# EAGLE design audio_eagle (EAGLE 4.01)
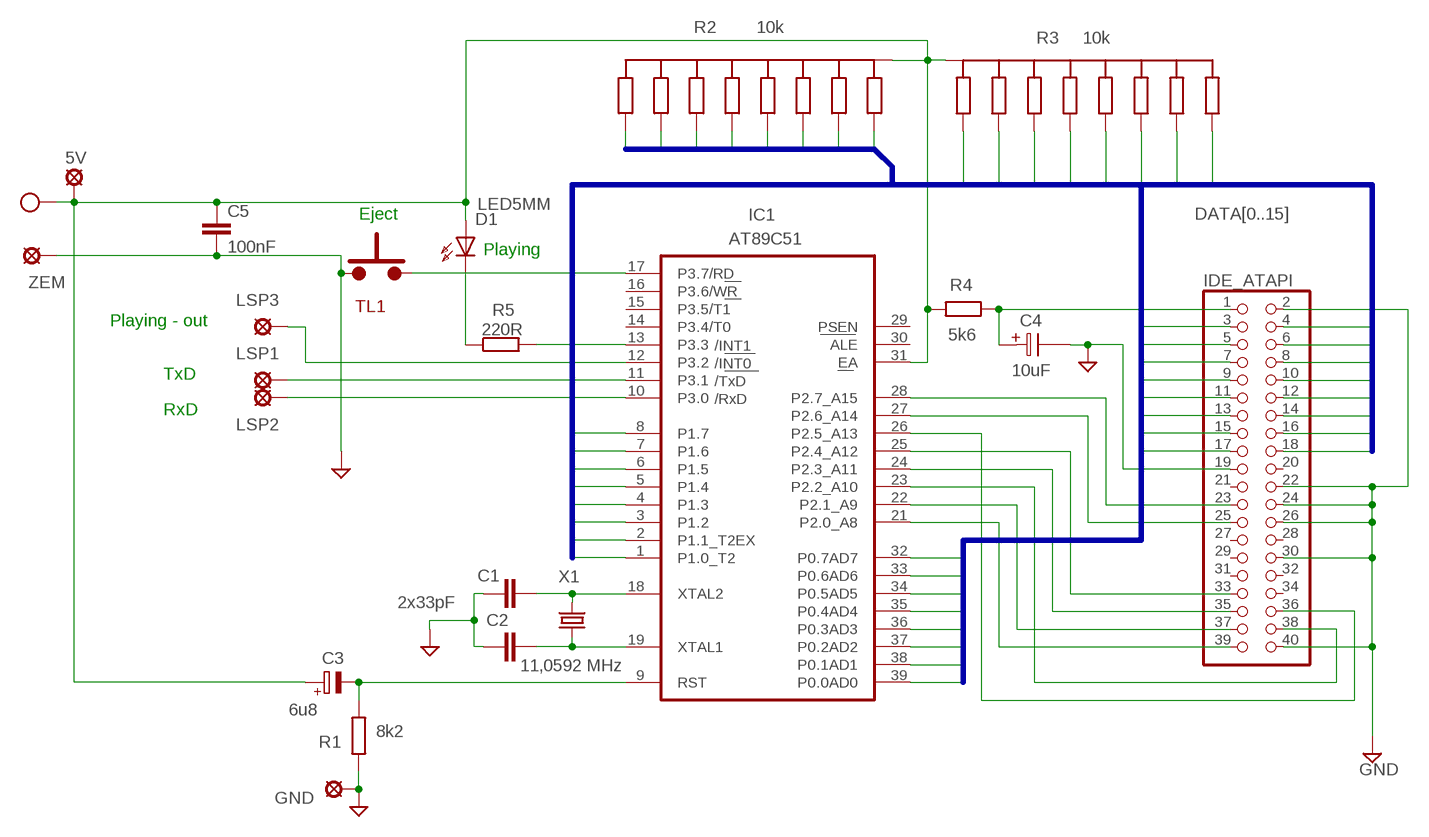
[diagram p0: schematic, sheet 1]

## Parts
5V  5V  LSP10  [LSP10]
C1  C-EU025-025X050  [C025-025X050]
C2  2x33pF  C-EU025-025X050  [C025-025X050]
C3  6u8  E2,5-5  [E2,5-5]
C4  10uF  CT07  [CT07]
C5  100nF  C-EU025-025X050  [C025-025X050]
D1  LED5MM  [LED5MM]
GND  LSP13  [LSP13]
IC1  AT89C51  AT89C52P  [DIL40]
IDE_ATAPI  PINHD-2X20  [2X20]
LSP1  TxD  LSP10  [LSP10]
LSP2  LSP10  [LSP10]
LSP3  LSP10  [LSP10]
R1  8k2  RR-10  [RR-10]
R2  10k  RR8X  [RR8X]
R3  10k  RR8X  [RR8X]
R4  5k6  RR-10  [RR-10]
R5  220R  R-EU_0207/10  [0207/10]
TL1  P-DT6  [P-DT6]
X1  11,0592 MHz  HC49U70  [HC49U70]
ZEM  GND  LSP10  [LSP10]

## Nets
DATA0: IC1.32(P0.7AD7) IDE_ATAPI.17 R2.9
DATA1: IC1.33(P0.6AD6) IDE_ATAPI.15 R2.8
DATA2: IC1.34(P0.5AD5) IDE_ATAPI.13 R2.7
DATA3: IC1.35(P0.4AD4) IDE_ATAPI.11 R2.6
DATA4: IC1.36(P0.3AD3) IDE_ATAPI.9 R2.5
DATA5: IC1.37(P0.2AD2) IDE_ATAPI.7 R2.4
DATA6: IC1.38(P0.1AD1) IDE_ATAPI.5 R2.3
DATA7: IC1.39(P0.0AD0) IDE_ATAPI.3 R2.2
DATA8: IC1.1(P1.0_T2) IDE_ATAPI.4 R3.2
DATA9: IC1.2(P1.1_T2EX) IDE_ATAPI.6 R3.3
DATA10: IC1.3(P1.2) IDE_ATAPI.8 R3.4
DATA11: IC1.4(P1.3) IDE_ATAPI.10 R3.5
DATA12: IC1.5(P1.4) IDE_ATAPI.12 R3.6
DATA13: IC1.6(P1.5) IDE_ATAPI.14 R3.7
DATA14: IC1.7(P1.6) IDE_ATAPI.16 R3.8
DATA15: IC1.8(P1.7) IDE_ATAPI.18 R3.9
GND: C1.2 C2.2 C4.2 C5.1 GND.MP IDE_ATAPI.2 IDE_ATAPI.19 IDE_ATAPI.22 IDE_ATAPI.24 IDE_ATAPI.26 IDE_ATAPI.30 IDE_ATAPI.40 R1.1 TL1.1 ZEM.MP
N$1: C1.1 IC1.18(XTAL2) X1.2
N$2: IC1.13(P3.3) R5.2
N$3: C2.1 IC1.19(XTAL1) X1.1
N$4: IC1.28(P2.7_A15) IDE_ATAPI.23
N$5: C3.- IC1.9(RST) R1.2
N$6: IC1.27(P2.6_A14) IDE_ATAPI.25
N$7: IC1.25(P2.4_A12) IDE_ATAPI.33
N$8: IC1.24(P2.3_A11) IDE_ATAPI.35
N$9: IC1.23(P2.2_A10) IDE_ATAPI.38
N$10: IC1.22(P2.1_A9) IDE_ATAPI.37
N$11: IC1.21(P2.0_A8) IDE_ATAPI.39
N$12: IC1.26(P2.5_A13) IDE_ATAPI.36
N$13: C4.1 IDE_ATAPI.1 R4.1
N$14: IC1.11(P3.1) LSP1.MP
N$15: IC1.10(P3.0) LSP2.MP
N$16: D1.K(C) R5.1
N$17: IC1.12(P3.2) LSP3.MP
N$18: IC1.17(P3.7/RD) TL1.2
VCC: 5V.MP C3.+ C5.2 D1.A IC1.31(EA) R2.1 R3.1 R4.2
Unconnected: IC1.14(P3.4/T0) IC1.15(P3.5/T1) IC1.16(P3.6/WR) IC1.29(PSEN) IC1.30(ALE) IDE_ATAPI.20 IDE_ATAPI.21 IDE_ATAPI.27 IDE_ATAPI.28 IDE_ATAPI.29 IDE_ATAPI.31 IDE_ATAPI.32 IDE_ATAPI.34

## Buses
DATA[0..15]

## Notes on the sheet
- Eject
- Playing
- Playing - out
- TxD
- RxD

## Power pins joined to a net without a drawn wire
GND: IC1.20(GND)
VCC: IC1.40(VCC)

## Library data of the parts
5V LSP1-LSP3 ZEM = solpad:LSP10: SOLDER PAD
C1 C2 C5 = rcl:C-EU: CAPACITOR, European symbol
C3 = polcap:E2,5-5
C4 = GM99:CT07
D1 = led:LED5MM: LED
GND = solpad:LSP13: SOLDER PAD
IC1 = atmel:AT89C52P: MICROCONTROLLER 8 Kbytes FLASH
IDE_ATAPI = pinhead:PINHD-2X20: PIN HEADER
R1 R4 = GM99:RR-10
R2 R3 = GM99:RR8X
R5 = rcl:R-EU_: RESISTOR, European symbol
TL1 = GM99:P-DT6
X1 = crystal:HC49U70: CRYSTAL

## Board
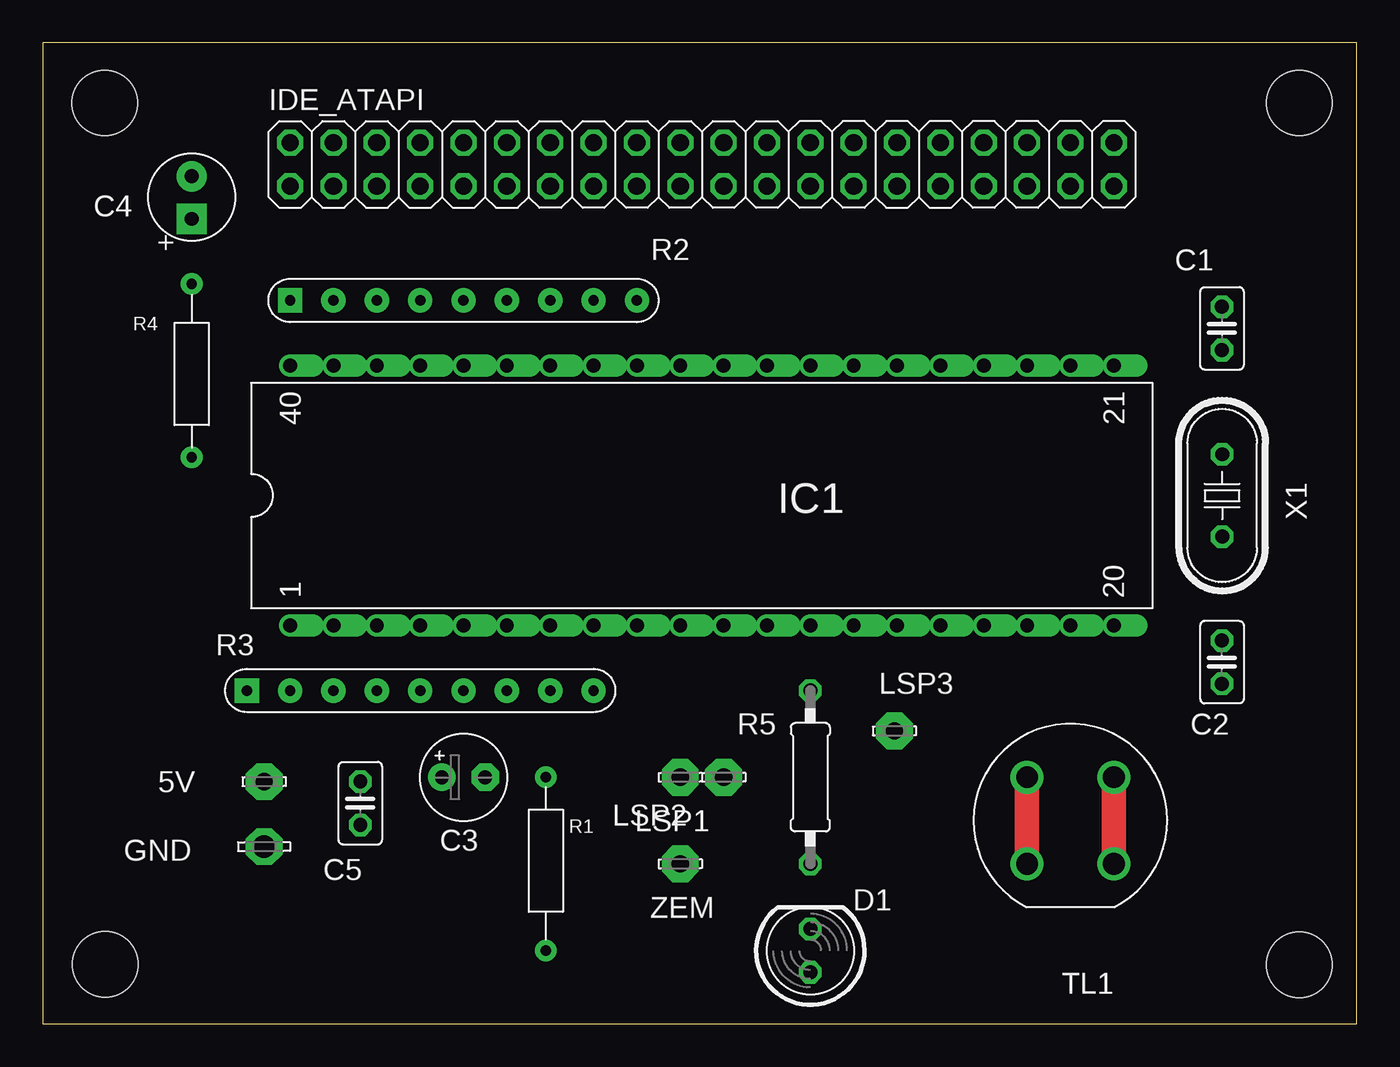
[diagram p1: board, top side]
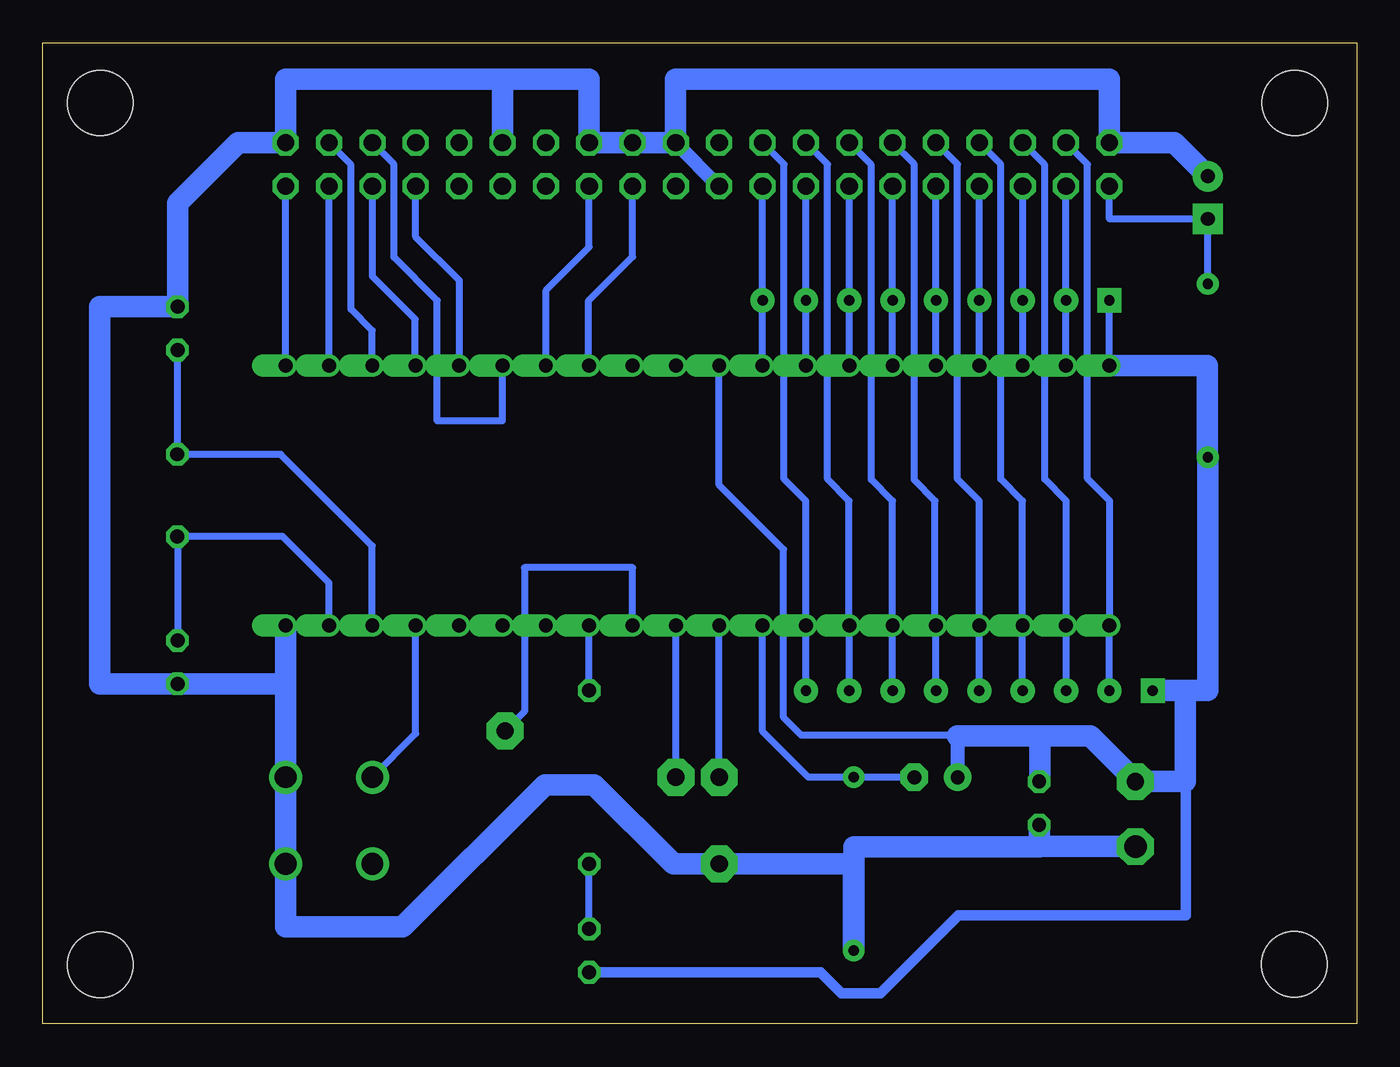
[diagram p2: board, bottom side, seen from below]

Size 77 x 57.5 mm. Coordinates in mm from the lower left corner, seen from the top.
Outline: 0,0 77,0 77,57.5 0,57.5 0,0
Copper layers used: Bottom
Holes 3.81 mm at 3.63,53.97 73.63,53.97 73.63,3.47 3.66,3.5

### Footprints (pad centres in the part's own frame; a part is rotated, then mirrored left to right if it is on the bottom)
LSP10 = drill 1.016 pad 2.159 octagon: MP 0,0
C025-025X050 = drill 0.813 octagon: 1 -1.27,0; 2 1.27,0
E2,5-5 = drill 0.813 pad 1.6 round: + -1.27,0 | drill 0.813 pad 1.6 octagon: - 1.27,0
CT07 = drill 0.813 pad 1.778 square: 1 0,0 | drill 0.813 pad 1.778 round: 2 2.5,0
LED5MM = drill 0.813 octagon: A -1.27,0; K 1.27,0
LSP13 = drill 1.321 pad 2.159 octagon: MP 0,0
DIL40 = drill 0.813 offset: 1 -24.13,-7.62; 2 -21.59,-7.62; 3 -19.05,-7.62; 4 -16.51,-7.62; 5 -13.97,-7.62; 6 -11.43,-7.62; 7 -8.89,-7.62; 8 -6.35,-7.62; 9 -3.81,-7.62; 10 -1.27,-7.62; 11 1.27,-7.62; 12 3.81,-7.62; 13 6.35,-7.62; 14 8.89,-7.62; 15 11.43,-7.62; 16 13.97,-7.62; 17 16.51,-7.62; 18 19.05,-7.62; 19 21.59,-7.62; 20 24.13,-7.62; 21 24.13,7.62; 22 21.59,7.62; 23 19.05,7.62; 24 16.51,7.62; 25 13.97,7.62; 26 11.43,7.62; 27 8.89,7.62; 28 6.35,7.62; 29 3.81,7.62; 30 1.27,7.62; 31 -1.27,7.62; 32 -3.81,7.62; 33 -6.35,7.62; 34 -8.89,7.62; 35 -11.43,7.62; 36 -13.97,7.62; 37 -16.51,7.62; 38 -19.05,7.62; 39 -21.59,7.62; 40 -24.13,7.62
2X20 = drill 1.016 octagon: 1 -24.13,-1.27; 2 -24.13,1.27; 3 -21.59,-1.27; 4 -21.59,1.27; 5 -19.05,-1.27; 6 -19.05,1.27; 7 -16.51,-1.27; 8 -16.51,1.27; 9 -13.97,-1.27; 10 -13.97,1.27; 11 -11.43,-1.27; 12 -11.43,1.27; 13 -8.89,-1.27; 14 -8.89,1.27; 15 -6.35,-1.27; 16 -6.35,1.27; 17 -3.81,-1.27; 18 -3.81,1.27; 19 -1.27,-1.27; 20 -1.27,1.27; 21 1.27,-1.27; 22 1.27,1.27; 23 3.81,-1.27; 24 3.81,1.27; 25 6.35,-1.27; 26 6.35,1.27; 27 8.89,-1.27; 28 8.89,1.27; 29 11.43,-1.27; 30 11.43,1.27; 31 13.97,-1.27; 32 13.97,1.27; 33 16.51,-1.27; 34 16.51,1.27; 35 19.05,-1.27; 36 19.05,1.27; 37 21.59,-1.27; 38 21.59,1.27; 39 24.13,-1.27; 40 24.13,1.27
RR-10 = drill 0.61 pad 1.27 round: 1 0,0; 2 10.16,0
RR8X = drill 0.61 pad 1.422 square: 1 0,0 | drill 0.61 pad 1.422 round: 2 2.54,0; 3 5.08,0; 4 7.62,0; 5 10.16,0; 6 12.7,0; 7 15.24,0; 8 17.78,0; 9 20.32,0
0207/10 = drill 0.813 octagon: 1 -5.08,0; 2 5.08,0
P-DT6 = drill 1.27 pad 1.93 round: 1 0,0; 1A 0,5.08; 2 5.08,0; 2A 5.08,5.08
HC49U70 = drill 0.813 octagon: 1 -2.413,0; 2 2.413,0

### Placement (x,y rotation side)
5V  12.97,14.2 0 top
C1  69.1,40.76 90 top
C2  69.1,21.2 270 top
C3  24.66,14.46 0 top
C4  8.73,47.17 90 top
C5  18.61,12.93 90 top
D1  44.98,4.3 90 top
GND  12.97,10.39 0 top
IC1  38.63,30.97 0 top
IDE_ATAPI  38.63,50.37 0 top
LSP1  39.9,14.46 0 top
LSP2  37.36,14.46 0 top
LSP3  49.91,17.17 0 top
R1  29.48,4.3 90 top
R2  14.5,42.4 0 top
R3  11.96,19.54 0 top
R4  8.73,43.36 270 top
R5  44.98,14.46 90 top
TL1  62.76,14.46 180 top
X1  69.11,30.97 90 top
ZEM  37.36,9.38 0 top

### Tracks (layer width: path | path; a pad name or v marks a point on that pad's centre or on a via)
DATA0
  Bottom 0.406: IC1.32 34.83,38.58 | IC1.32 | IC1.32 R2.9 34.82,49.09 IDE_ATAPI.17 | IDE_ATAPI.17 34.85,49.12 | IDE_ATAPI.17
DATA1
  Bottom 0.406: 32.27,38.59 32.26,38.58 | IC1.33 32.27,38.59 | 32.27,38.59 IC1.33 R2.8 IDE_ATAPI.15 | IDE_ATAPI.15 | IDE_ATAPI.15 32.29,49.12
DATA2
  Bottom 0.406: IC1.34 29.75,38.58 | IC1.34 | IC1.34 R2.7 IDE_ATAPI.13 | IDE_ATAPI.13 | IDE_ATAPI.13 29.72,49.12
DATA3
  Bottom 0.406: R2.6 27.21,42.39 27.2,42.38 IC1.35 | R2.6 | IDE_ATAPI.11 27.2,49.08 27.21,49.07 27.2,49.06 R2.6
DATA4
  Bottom 0.406: 24.66,49.14 IDE_ATAPI.9 | 24.66,49.14 R2.5 IC1.36 | 24.66,49.14 24.67,49.14 | IC1.36 24.67,38.58 | IC1.36
DATA5
  Bottom 0.406: IC1.37 22.12,38.58 | 22.12,38.58 R2.4 22.12,49.06 22.13,49.07 22.12,49.08 IDE_ATAPI.7 | 22.12,38.58 22.13,38.58
DATA6
  Bottom 0.406: 19.58,42.39 R2.3 19.58,49.09 IDE_ATAPI.5 | IC1.38 19.58,42.39 | 19.58,42.39 19.59,42.39
DATA7
  Bottom 0.406: IDE_ATAPI.3 | IDE_ATAPI.3 R2.2 IC1.39 | IDE_ATAPI.3 17.02,49.12 | IC1.39 17.05,38.58 | IC1.39
DATA8
  Bottom 0.406: IC1.1 14.51,23.34 | R3.2 14.51,23.34 | IDE_ATAPI.4 15.78,50.37 15.78,31.95 14.48,30.65 14.48,23.36 14.51,23.34 | 14.51,23.34 IC1.1 | IC1.1
DATA9
  Bottom 0.406: R3.3 17.02,19.54 17.02,23.31 | 17.02,23.34 IC1.2 17.03,23.34 17.02,23.34 | IDE_ATAPI.6 18.29,50.35 18.29,31.92 17.02,30.65 17.02,23.31 | 17.02,23.31 17.02,23.34
DATA10
  Bottom 0.406: R3.4 19.59,23.31 | 19.59,23.31 IC1.3 19.58,23.32 19.59,23.31 | IDE_ATAPI.8 20.86,50.37 20.86,31.92 19.59,30.65 19.59,23.31
DATA11
  Bottom 0.406: R3.5 IC1.4 | IC1.4 22.1,23.36 | IDE_ATAPI.10 23.4,50.37 23.4,31.92 22.13,30.65 22.13,23.31 22.12,23.32 IC1.4
DATA12
  Bottom 0.406: 24.68,23.34 24.69,23.34 24.66,23.3 R3.6 | 24.68,23.34 IC1.5 | IDE_ATAPI.12 25.94,50.37 25.94,31.87 24.72,30.65 24.72,23.39 24.68,23.36 24.68,23.34
DATA13
  Bottom 0.406: IC1.6 | R3.7 IC1.6 | IC1.6 27.21,23.36 | IDE_ATAPI.14 28.45,50.35 28.45,31.9 27.21,30.65 27.21,23.34 IC1.6
DATA14
  Bottom 0.406: R3.8 IC1.7 | IC1.7 29.72,23.36 | IDE_ATAPI.16 31.02,50.37 31.02,31.92 29.75,30.65 29.75,23.34 IC1.7 | IC1.7
DATA15
  Bottom 0.406: IDE_ATAPI.18 33.56,50.37 33.56,31.92 32.29,30.65 32.29,23.34 IC1.8 | IC1.8 | R3.9 32.29,19.53 | R3.9 | IC1.8 R3.9
GND
  Bottom 0.406: 37.39,49.09 IDE_ATAPI.19 | IDE_ATAPI.22 39.9,51.6
  Bottom 0.813: 39.9,51.6 37.39,49.09
  Bottom 1.27: C4.2 | C4.2 10.7,51.63 IDE_ATAPI.2 14.5,55.37 39.91,55.37 IDE_ATAPI.22 | IDE_ATAPI.22 | IDE_ATAPI.22 IDE_ATAPI.24 | IDE_ATAPI.24 42.5,51.63 42.5,51.66 | IDE_ATAPI.26 IDE_ATAPI.24 | IDE_ATAPI.26 44.99,51.66 | IDE_ATAPI.26 44.98,55.37 50.19,55.37 | IDE_ATAPI.30 50.06,55.37 50.19,55.37 | 60.4,55.37 50.19,55.37 | 60.4,55.37 60.48,55.37 | 60.4,55.37 62.76,55.37 IDE_ATAPI.40 65.56,51.63 69.09,48.1 C1.2 | C1.2 69.12,42.01 | C1.2 | C1.2 73.66,42.02 73.66,19.93 C2.2 | C2.2 | C2.2 62.77,19.93 | IC1.20 62.77,19.93 | 62.77,19.93 62.77,14.45 62.76,14.45 TL1.1 62.77,5.68 55.91,5.68 47.58,14.02 44.68,14.02 40.04,9.38 ZEM.MP 29.49,9.38 29.49,4.29 R1.1 29.47,4.29 29.47,10.38 18.61,10.38 C5.1 18.6,11.66 | 18.6,11.66 18.6,11.68 | GND.MP 18.6,10.39 18.6,11.66
N$1
  Bottom 0.406: 57.69,23.34 | IC1.18 57.69,23.34 | 57.69,23.34 57.69,28.01 63.05,33.38 X1.2 | X1.2 | C1.1 69.1,33.37 X1.2
N$2
  Bottom 0.406: R5.2 44.98,19.53 | 44.98,19.53 IC1.13 | 44.98,19.53 44.99,19.53
N$3
  Bottom 0.406: IC1.19 60.22,25.84 62.94,28.57 69.12,28.57 | 69.12,28.57 X1.1 69.11,28.57 69.12,28.57 | C2.1 69.1,28.57 69.12,28.57
N$4
  Bottom 0.406: IDE_ATAPI.23 42.44,44.96 45.01,42.39 45.01,38.6 45,38.6 IC1.28
N$5
  Bottom 0.406: C3.- R1.2 | R1.2 29.49,14.46 29.49,14.45 | IC1.9 34.82,17.13 32.13,14.45 29.49,14.45 | 29.49,14.45 | R1.2 29.49,14.45
N$6
  Bottom 0.406: IDE_ATAPI.25 44.98,45.52 47.5,43 47.5,38.6 IC1.27
N$7
  Bottom 0.406: IDE_ATAPI.33 55.14,46.11 52.58,43.56 52.58,38.57 | 52.58,38.57 52.58,38.55 | IC1.25 52.58,38.57
N$8
  Bottom 0.406: IDE_ATAPI.35 57.68,43.8 55.17,41.3 55.17,38.6 55.16,38.6 IC1.24
N$9
  Bottom 0.406: IDE_ATAPI.38 58.93,50.35 58.93,41.88 57.69,40.63 57.69,38.58 | 57.69,38.58 | IC1.23 57.69,38.58
N$10
  Bottom 0.406: IC1.22 60.22,38.55 | 60.22,38.55 IDE_ATAPI.37 | 60.22,38.55 60.23,38.55
N$11
  Bottom 0.406: IC1.21 62.76,38.58 | 62.76,38.58 IDE_ATAPI.39 | 62.76,38.58 62.77,38.58
N$12
  Bottom 0.406: IDE_ATAPI.36 56.42,50.37 56.42,44.93 53.88,42.39 53.88,35.33 50.07,35.33 IC1.26 | IC1.26 50.07,38.6 | IC1.26
N$13
  Bottom 0.406: C4.1 | IDE_ATAPI.1 14.5,47.16 C4.1 | R4.1 8.73,43.38 | 8.73,43.38 C4.1 | 8.73,43.38 8.74,43.38
N$14
  Bottom 0.406: 39.9,23.34 IC1.11 | LSP1.MP 39.9,23.34 | 39.9,23.34 39.91,23.34
N$15
  Bottom 0.406: 37.36,23.34 IC1.10 | LSP2.MP 37.36,23.34 | 37.36,23.34 37.37,23.34
N$16
  Bottom 0.406: D1.K 44.96,5.58 44.98,5.6 R5.1
N$17
  Bottom 0.406: IC1.12 42.44,26.74 48.77,26.74 48.77,18.31 LSP3.MP | LSP3.MP
N$18
  Bottom 0.406: 57.71,14.46 57.71,14.45 | TL1.2 57.71,14.46 | IC1.17 55.14,17.02 57.71,14.46
VCC
  Bottom 0.406: IC1.40 14.51,38.58 | IC1.40 | R2.1 IC1.40 | IC1.31 37.36,31.58 33.58,27.81 33.58,17.95 32.54,16.91 23.95,16.91 | 23.95,16.91 23.9,16.91 | 23.39,16.91 23.95,16.91
  Bottom 0.61: D1.A 31.43,3.03 30.2,1.8 27.92,1.8 23.35,6.37 10.01,6.37 10.01,14.25 10.04,14.22
  Bottom 0.813: 18.57,14.46 C5.2 | 12.96,14.22 5V.MP | 23.39,16.89 23.39,16.91 | 23.39,16.89 23.4,16.89 | 23.39,16.89 C3.+
  Bottom 1.27: IC1.40 8.77,38.59 8.77,33.22 8.73,33.22 R4.2 8.73,19.53 11.96,19.53 | 11.96,19.53 11.97,19.53 | 11.96,19.53 R3.1 | 11.96,19.53 10.04,19.53 10.04,14.22 12.93,14.22 12.96,14.19 5V.MP | 18.57,16.89 22.96,16.89 23.39,16.89 | 18.57,16.89 18.57,14.46 | 18.57,16.89 15.62,16.89 12.96,14.22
